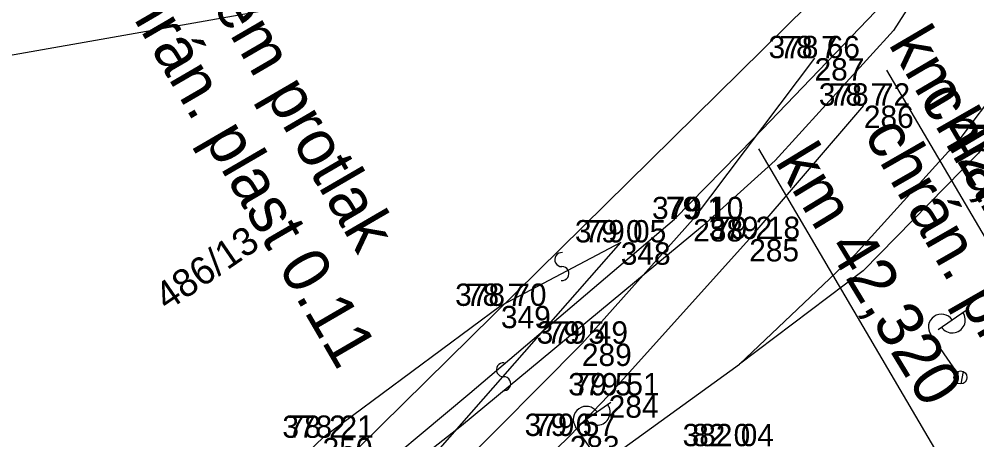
# Model space of a CAD drawing. Extents: x -514509 to -512782, y -1144610 to -1143439.
# Drawn here: x -513532.1 to -513480.6, y -1143698.6 to -1143676 of the extents above; entities that cross this region are included whole.
import ezdxf

# ---------------------------------------------------------------- set-up
doc = ezdxf.new("R2010")
doc.units = 0
for name, color, linetype in [('Vrstva 10', 7, 'Continuous'), ('Vrstva 18', 7, 'Continuous'), ('Vrstva 25', 7, 'Continuous'), ('Vrstva 37', 7, 'Continuous'), ('Vrstva 57', 7, 'Continuous'), ('Vrstva 58', 7, 'Continuous'), ('Vrstva 59', 7, 'Continuous'), ('Vrstva 6', 7, 'Continuous'), ('Vrstva 60', 7, 'Continuous'), ('Vrstva 62', 7, 'Continuous'), ('Vrstva 8', 7, 'Continuous'), ('Vrstva 9', 7, 'Continuous')]:
    doc.layers.add(name, color=color, linetype=linetype)

msp = doc.modelspace()

# ---------------------------------------------------------------- linework, layer by layer
at = {"layer": 'Vrstva 10'}
for points in [[(-513489.364, -1143678.135), (-513495.881, -1143686.783), (-513501.86, -1143693.473), (-513508.622, -1143700.288), (-513516.941, -1143708.421), (-513526.473, -1143717.513), (-513535.33, -1143725.812), (-513542.764, -1143732.375), (-513549.349, -1143738.64), (-513555.353, -1143744.777)], [(-513500.422, -1143696.255), (-513492.874, -1143687.855), (-513486.706, -1143680.678)], [(-513524.979, -1143713.369), (-513510.64, -1143700.403), (-513499.767, -1143688.028), (-513506.21, -1143691.442), (-513515.785, -1143698.53)], [(-513502.507, -1143698.431), (-513500.422, -1143696.255)], [(-513510.098, -1143705.844), (-513502.507, -1143698.431)]]:
    msp.add_lwpolyline(points, dxfattribs=at)
msp.add_spline([(-513515.785, -1143698.53), (-513521.525, -1143703.643), (-513529.686, -1143709.146), (-513538.15, -1143717.214), (-513544.213, -1143722.812)], degree=3, dxfattribs=at)
at = {"layer": 'Vrstva 18'}
for centre, radius, start, end in [((-513502.944, -1143688.952), 0.376, 84.3625, 270.6736), ((-513502.931, -1143689.705), 0.377, 263.6864, 91.3496), ((-513506.075, -1143694.87), 0.376, 84.3625, 270.6736), ((-513506.062, -1143695.623), 0.377, 263.6864, 91.3496)]:
    msp.add_arc(centre, radius, start, end, dxfattribs=at)
at = {"layer": 'Vrstva 25'}
msp.add_lwpolyline([(-513465.103, -1143715.641), (-513470.183, -1143706.847), (-513476.151, -1143710.606), (-513492.352, -1143682.995)], dxfattribs=at)
at = {"layer": 'Vrstva 37'}
msp.add_lwpolyline([(-513485.487, -1143678.771), (-513465.491, -1143712.764)], dxfattribs=at)
at = {"layer": 'Vrstva 6'}
for p, q in [((-513482.712, -1143692.705), (-513481.218, -1143691.667)), ((-513481.717, -1143694.997), (-513483.115, -1143692.985)), ((-513481.734, -1143695.559), (-513481.625, -1143694.953)), ((-513481.48, -1143695.631), (-513481.362, -1143694.972)), ((-513501.794, -1143697.66), (-513500.3, -1143696.622)), ((-513500.799, -1143699.952), (-513502.197, -1143697.94))]:
    msp.add_line(p, q, dxfattribs=at)
msp.add_circle((-513481.518, -1143695.285), 0.35, dxfattribs=at)
msp.add_circle((-513481.518, -1143695.285), 0.35, dxfattribs=at)
for centre, start, end in [((-513482.54, -1143692.585), 34.7832, 214.7832), ((-513481.96, -1143692.193), 214.0806, 35.4858), ((-513501.622, -1143697.54), 34.7832, 214.7832), ((-513501.042, -1143697.148), 214.0806, 35.4858)]:
    msp.add_arc(centre, 0.7, start, end, dxfattribs=at)
at = {"layer": 'Vrstva 60'}
for p, q in [((-513489.36, -1143678.13), (-513489.36, -1143678.13)), ((-513486.71, -1143680.68), (-513486.71, -1143680.68)), ((-513495.88, -1143686.78), (-513495.88, -1143686.78)), ((-513499.77, -1143688.03), (-513499.77, -1143688.03)), ((-513492.87, -1143687.85), (-513492.87, -1143687.85)), ((-513506.21, -1143691.44), (-513506.21, -1143691.44)), ((-513501.86, -1143693.47), (-513501.86, -1143693.47)), ((-513500.42, -1143696.25), (-513500.42, -1143696.25)), ((-513515.79, -1143698.53), (-513515.79, -1143698.53)), ((-513502.51, -1143698.43), (-513502.51, -1143698.43))]:
    msp.add_line(p, q, dxfattribs=at)
at = {"layer": 'Vrstva 8'}
for p, q in [((-513481.481, -1143682.388), (-513475.438, -1143674.345)), ((-513495.386, -1143687.158), (-513508.331, -1143697.888)), ((-513503.11, -1143701.59), (-513493.388, -1143694.566))]:
    msp.add_line(p, q, dxfattribs=at)
for points in [[(-513446.005, -1143691.624), (-513470.031, -1143652.864), (-513469.93, -1143661.143), (-513470.8, -1143666.616), (-513473.257, -1143673.241), (-513480.547, -1143683.23), (-513486.741, -1143689.555), (-513493.388, -1143694.566), (-513487.156, -1143688.669), (-513481.481, -1143682.388)], [(-513479.738, -1143653.763), (-513477.339, -1143660.72), (-513480.136, -1143668.853), (-513485.123, -1143676.639), (-513491.478, -1143683.634), (-513495.386, -1143687.158)], [(-513538.877, -1143679.071), (-513483.704, -1143669.334), (-513513.863, -1143699.065), (-513532.594, -1143713.255)], [(-513543.007, -1143722.265), (-513531.849, -1143715.02), (-513522.804, -1143707.729), (-513514.307, -1143701.502), (-513507.877, -1143696.134), (-513496.887, -1143686.782), (-513492.629, -1143682.433), (-513485.641, -1143675.148)], [(-513508.331, -1143697.888), (-513520.548, -1143707.483), (-513532.171, -1143716.358), (-513542.292, -1143722.743)]]:
    msp.add_lwpolyline(points, dxfattribs=at)

# ---------------------------------------------------------------- texts
at = {"layer": 'Vrstva 25'}
msp.add_text('km 42,320', height=2.5, rotation=301.3053, dxfattribs=at).set_placement((-513491.51, -1143683.7))
at = {"layer": 'Vrstva 37'}
msp.add_text('km 42,321', height=2.5, rotation=300.45, dxfattribs=at).set_placement((-513485.421, -1143677.37))
at = {"layer": 'Vrstva 57'}
for s, p in [('78 7 ', (-513491.243, -1143678.13)), ('78 7 ', (-513488.593, -1143680.68)), ('79 1 ', (-513497.344, -1143686.78)), ('79 0 ', (-513501.724, -1143688.03)), ('79 2 ', (-513494.76, -1143687.85)), ('78 7 ', (-513508.093, -1143691.44)), ('79 5 ', (-513503.75, -1143693.47)), ('79 5 ', (-513502.31, -1143696.25)), ('78 2 ', (-513517.673, -1143698.53)), ('79 6 ', (-513504.441, -1143698.43)), ('82 0 ', (-513495.938, -1143698.98))]:
    msp.add_text(s, height=1.2, dxfattribs=at).set_placement(p)
at = {"layer": 'Vrstva 58'}
for s, p in [('378 66', (-513491.83, -1143678.13)), ('378 72', (-513489.131, -1143680.68)), ('379 10', (-513498.092, -1143686.78)), ('379 05', (-513502.236, -1143688.03)), ('379 18', (-513495.043, -1143687.85)), ('378 70', (-513508.67, -1143691.44)), ('379 49', (-513504.292, -1143693.47)), ('379 51', (-513502.593, -1143696.25)), ('378 21', (-513517.956, -1143698.53)), ('379 57', (-513504.938, -1143698.43)), ('382 04', (-513496.45, -1143698.98))]:
    msp.add_text(s, height=1.2, dxfattribs=at).set_placement(p)
at = {"layer": 'Vrstva 59'}
for s, p in [('287', (-513489.36, -1143679.33)), ('286', (-513486.71, -1143681.88)), ('288', (-513495.88, -1143687.98)), ('348', (-513499.77, -1143689.23)), ('285', (-513492.87, -1143689.05)), ('349', (-513506.21, -1143692.64)), ('289', (-513501.86, -1143694.67)), ('284', (-513500.42, -1143697.45)), ('350', (-513515.79, -1143699.73)), ('283', (-513502.51, -1143699.63))]:
    msp.add_text(s, height=1.2, dxfattribs=at).set_placement(p)
at = {"layer": 'Vrstva 62'}
for s, rotation, p in [('pod vjezdem protlak', 300.1817, (-513528.936, -1143662.875)), ('chrán. plast 0.11', 300.1817, (-513527.369, -1143673.597)), ('chrán. plast 0.15', 299.8281, (-513483.752, -1143680.264)), ('chrán. plast 0.15', 299.8281, (-513483.752, -1143680.264)), ('chrán. plast 0.15', 299.8281, (-513486.737, -1143682.222))]:
    msp.add_text(s, height=2.5, rotation=rotation, dxfattribs=at).set_placement(p)
at = {"layer": 'Vrstva 9'}
msp.add_text('486/13', height=1.5, rotation=34.4019, dxfattribs=at).set_placement((-513524.143, -1143691.749))

doc.saveas('drawing.dxf')
